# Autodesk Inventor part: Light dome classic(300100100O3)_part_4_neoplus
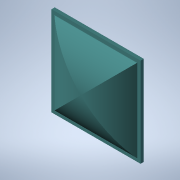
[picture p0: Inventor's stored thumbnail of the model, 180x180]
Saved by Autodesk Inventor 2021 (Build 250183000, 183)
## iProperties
Created: 2026-04
Part Number: Light dome classic(300100100O3)_part_4_neoplus
Material: Generic
Catalog Web Link: www.3dfindit.com
Description: Light dome classic_part_4_neoplus-
Vendor: KINGSPAN
Document SubType Name: Modeling
Designer: psAdmin
Manufacturer: KINGSPAN
Mass: 68121.5 g
Surface Area: 17559.1 cm^2
Volume: 68121.5 cm^3
Density: 1 g/cm^3
Appearance: PSOLRGB-194-255-255
Category: PARTsolutions
Company: KINGSPAN
Title: Light dome classic(300100100O3)_part_4_neoplus
Author: Cadenas PARTsolutions
PSOL_IDENT_0: {$CADENAS_DATA/23d-libs/kingspan_kla/light_dome_classic_neoplus/parts/part_4.prj},278 {VTYP=3D},{NB=
PSOL_IDENT_1: Light dome classic(300100100O3)_part_4_neoplus},{LINA=Light dome classic(300100100O3)_part_4_neoplus
PSOL_IDENT_2: },{NN=Light dome classic_part_4_neoplus},{DATE=20.03.2025 09:30:52},{GEOMDATE=01.07.2024 05:57:57},{
PSOL_IDENT_3: VERSION=},{LINEID=10},{WBVAR=LODLEVEL,L,W,TG,TS},{WBNUMERIC=W}  {NB=Light dome classic(300100100O3)_
PSOL_IDENT_4: part_4_neoplus},{LINA=Light dome classic(300100100O3)_part_4_neoplus},{KT=DUMMY},{IDNR=},{PN=Light d
PSOL_IDENT_5: ome classic},{LODLEVEL=300},{L=100},{W=100},{WX=100,150,200,250,300},{TG=O},{TS=3},{TSX='3','acrylic
PSOL_IDENT_6: shell with Polycarbonate','4','2 layers of acrylic shell + 1  Polycarbonate panel','5','1 layers of
PSOL_IDENT_7: acrylic shell + 1 polycarbonate panel + aerogel'},{LX=1000},{XWX=1000},{VER=2},{HEI=1048.274},{TOP=
PSOL_IDENT_8: 300},{NO=2},{HEIGHT=180},{SEC=30}
NB: Light dome classic(300100100O3)_part_4_neoplus
NN: Light dome classic_part_4_neoplus
NBSYN: $PN.($LODLEVEL.$L.$W.$TG.$TS.)_part_4_neoplus
LINA: Light dome classic(300100100O3)_part_4_neoplus
CATALOG: Light + Air
PN: Light dome classic
LODLEVEL: 300
L: 100
W: 100
TG: opal
TS: acrylic shell with Polycarbonate
SUPPLIER: KINGSPAN
ARTICLENO: Light dome classic(300100100O3)_part_4_neoplus
BOMINFO: Light dome classic(300100100O3)_part_4_neoplus
CREATOR: CADENAS GmbH
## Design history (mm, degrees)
sketch "Sketch_9"
  geometry: L1 (400, 0)-(400, 106.946); L2 (-400, 106.946)-(-400, 0); L3 (-400, 0)-(400, 0); A1 r 624.224 centre (0, -372.278) between (400, 106.946) and (-400, 106.946)
  constraints: 6 end point, 2 point on circle, 1 centre point
extrude "Extrusion1" join sketch "Sketch_9" stored distance "d0" = 1000; taper "d1" = 0 deg
sketch "Sketch_2"
  geometry: L1 (506, 103.596)-(-506, 103.596); L2 (-506, 103.596)-(-506, 71.946); L3 (-506, 71.946)-(506, 71.946); L4 (506, 71.946)-(506, 103.596)
  constraints: 8 end point
extrude "Extrusion2" join sketch "Sketch_2" stored distance "d2" = 2000; taper "d3" = 0 deg
sketch "Sketch_3"
  geometry: L1 (-530, 103.596)-(-530, 71.946); L2 (-530, 71.946)-(530, 71.946); L3 (530, 71.946)-(530, 103.596); L4 (530, 103.596)-(-530, 103.596)
  constraints: 8 end point
extrude "Extrusion3" join sketch "Sketch_3" stored distance "d4" = 2000; taper "d5" = 0 deg
sketch "Sketch_4"
  geometry: L1 (-1433, 103.596)-(-1433, -128.054); L2 (-1433, -128.054)-(1433, -128.054); L3 (1433, -128.054)-(1433, 103.596); L4 (1433, 103.596)-(433, 103.596); L5 (433, 103.596)-(433, 71.946); L6 (433, 71.946)-(-433, 71.946); L7 (-433, 71.946)-(-433, 103.596); L8 (-433, 103.596)-(-1433, 103.596)
  constraints: 16 end point
extrude "Extrusion4" cut sketch "Sketch_4" stored distance "d6" = 2000; taper "d7" = 0 deg
sketch "Sketch_17"
  geometry: L1 (1000, -16104.45)-(-1000, -16104.45); L2 (-135, 100)-(-135, -106.95); L3 (-135, -106.95)-(135, -106.95); L4 (135, -106.95)-(135, 100); A1 r 1825 centre (0, -1720) between (135, 100) and (-135, 100)
  constraints: 8 end point, 2 point on circle, 1 centre point
revolve "Revolution1" sketch "Sketch_17" stored, may be unused: angle "d8" = 360 deg
sketch "Sketch_13"
  geometry: L1 (432, 103.596)-(380, 103.596); L2 (380, 103.596)-(380, 71.946); L3 (380, 71.946)-(-380, 71.946); L4 (-380, 71.946)-(-380, 103.596); L5 (-380, 103.596)-(-432, 103.596); L6 (-432, 103.596)-(-432, 61.946); L7 (-432, 61.946)-(432, 61.946); L8 (432, 61.946)-(432, 103.596)
  constraints: 16 end point
extrude "Extrusion5" join sketch "Sketch_13" stored distance "d9" = 1000; taper "d10" = 0 deg
sketch "Sketch_14"
  geometry: L1 (1400, 103.596)-(432, 103.596); L2 (432, 103.596)-(432, 71.946); L3 (432, 71.946)-(-432, 71.946); L4 (-432, 71.946)-(-432, 103.596); L5 (-432, 103.596)-(-1400, 103.596); L6 (-1400, 103.596)-(-1400, -128.054); L7 (-1400, -128.054)-(1400, -128.054); L8 (1400, -128.054)-(1400, 103.596)
  constraints: 16 end point
extrude "Extrusion6" cut sketch "Sketch_14" stored distance "d11" = 2000; taper "d12" = 0 deg
sketch "Sketch_15"
  geometry: L1 (1424, 1333.333)-(-1424, 1333.333); L2 (-1424, 1333.333)-(-1424, 0); L3 (-1424, 0)-(-433, 0); L4 (-433, 0)-(-433, 103.596); L5 (-433, 103.596)-(-400, 103.596); L6 (-400, 103.596)-(-400, 106.946); L7 (400, 106.946)-(400, 103.596); L8 (400, 103.596)-(433, 103.596); L9 (433, 103.596)-(433, 0); L10 (433, 0)-(1424, 0); L11 (1424, 0)-(1424, 1333.333); A1 r 624.224 centre (0, -372.278) between (400, 106.946) and (-400, 106.946)
  constraints: 22 end point, 2 point on circle, 1 centre point
extrude "Extrusion7" cut sketch "Sketch_15" stored distance "d13" = 1000; taper "d14" = 0 deg
node "IP_4_XY"
node "IP_4_YZ"
node "IP_4_ZX"
node "IP_4_X"
node "IP_4_Y"
node "IP_4_Z"
node "IP_4_Center"
body "Solid1"
other parameters: "d15" = 0
